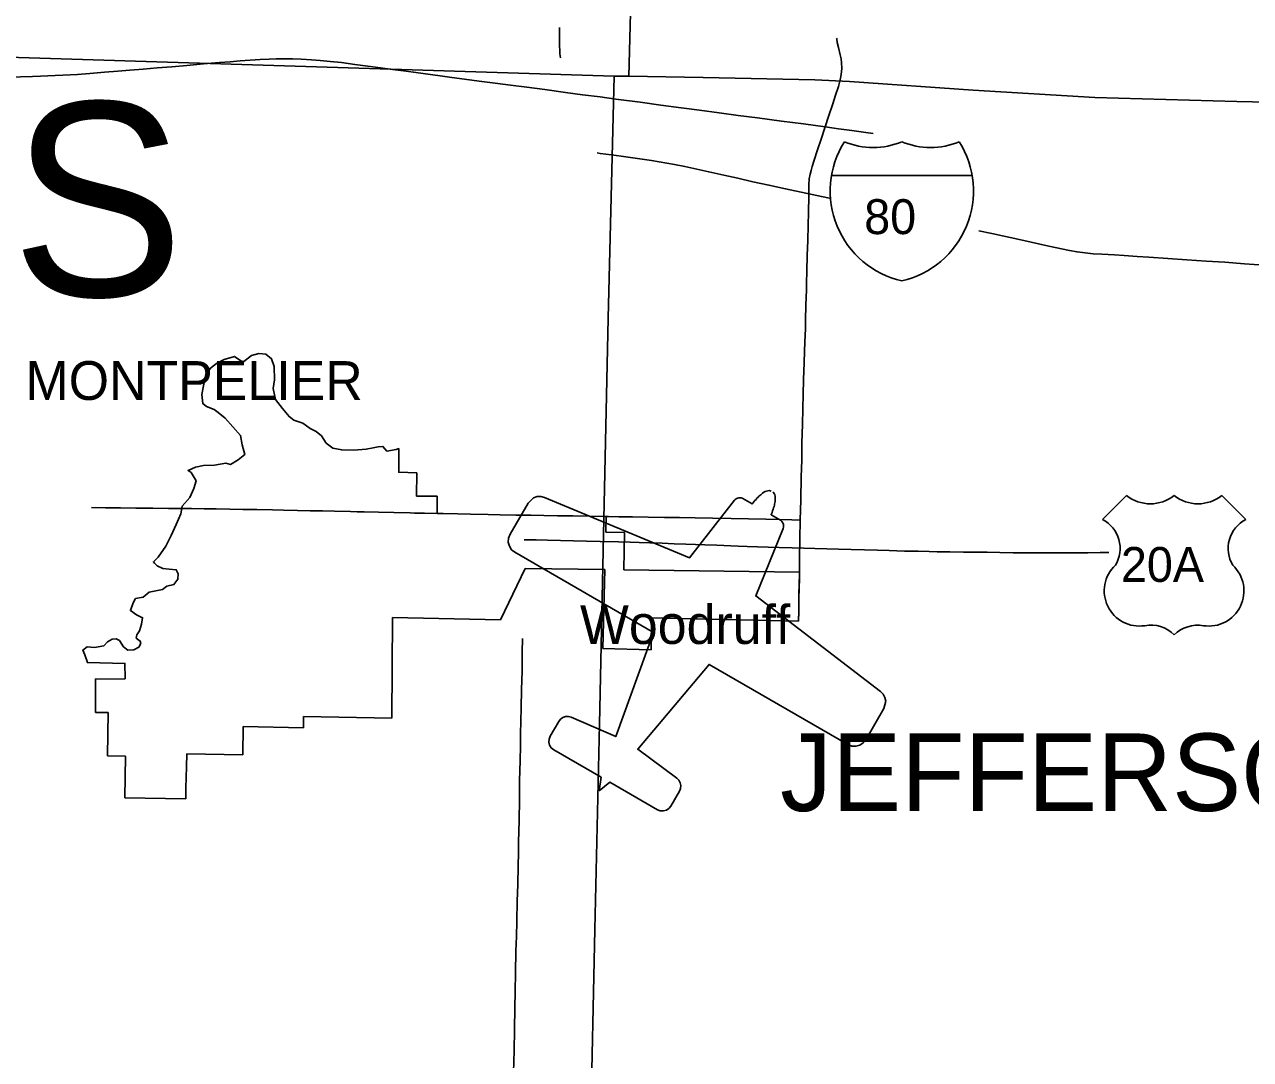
# Model space of a CAD drawing. Extents: x -232 to 448, y 619 to 1059.
# Drawn here: x -131.55 to -99.12, y 896.53 to 923.91 of the extents above; entities that cross this region are included whole.
import ezdxf

# ---------------------------------------------------------------- set-up
doc = ezdxf.new("R2010")
doc.units = 0
doc.layers.add('Default', color=7, linetype='Continuous')

msp = doc.modelspace()

# ---------------------------------------------------------------- linework, layer by layer
at = {"layer": 'Default'}
for p, q in [((-110.207, 919.917), (-106.487, 919.917)), ((-102.405, 911.449), (-103.039, 910.815)), ((-102.405, 911.449), (-103.039, 910.815)), ((-99.249, 910.815), (-99.884, 911.449)), ((-99.249, 910.815), (-99.884, 911.449)), ((-116.178, 910.485), (-116.168, 910.896)), ((-115.677, 910.472), (-116.178, 910.485)), ((-115.703, 909.487), (-115.677, 910.472)), ((-118.965, 908.164), (-118.31, 909.522)), ((-121.816, 908.226), (-118.965, 908.164)), ((-114.977, 907.371), (-114.958, 908.218)), ((-116.255, 907.401), (-114.977, 907.371)), ((-129.335, 905.708), (-129.355, 904.565)), ((-125.778, 904.593), (-125.764, 905.338)), ((-125.764, 905.338), (-124.173, 905.309)), ((-128.88, 904.556), (-128.899, 903.457)), ((-127.26, 904.619), (-125.778, 904.593)), ((-128.899, 903.457), (-127.286, 903.428))]:
    msp.add_line(p, q, dxfattribs=at)
for points in [[(-114.736, 953.989), (-115.571, 922.539)], [(-148.03, 923.551), (-115.954, 922.545)], [(-117.4, 923.827), (-117.401, 923.701), (-117.398, 923.516), (-117.4, 923.333), (-117.396, 923.23), (-117.39, 923.137), (-117.373, 923.032)], [(-110.071, 923.549), (-110.069, 923.532), (-110.054, 923.435), (-110.022, 923.305), (-109.975, 923.104), (-109.952, 923.005), (-109.938, 922.892), (-109.935, 922.758), (-109.941, 922.657), (-109.958, 922.538), (-109.982, 922.407), (-110.022, 922.272), (-110.097, 922.043), (-110.174, 921.811), (-110.284, 921.474), (-110.374, 921.204)], [(-131.977, 922.517), (-131.342, 922.531), (-131.124, 922.54), (-130.152, 922.589), (-129.826, 922.616), (-129.438, 922.649), (-129.084, 922.678), (-128.766, 922.702), (-128.413, 922.731), (-128.044, 922.762), (-127.658, 922.794), (-127.256, 922.825), (-126.817, 922.866), (-126.39, 922.902), (-126.115, 922.925), (-125.847, 922.948), (-125.581, 922.966), (-125.319, 922.981), (-125.08, 922.996), (-124.895, 923.002), (-124.711, 923.005), (-124.464, 923.001), (-124.23, 922.994), (-123.958, 922.975), (-123.728, 922.96), (-123.469, 922.934), (-123.171, 922.902), (-122.816, 922.853), (-122.467, 922.809), (-122.133, 922.762), (-121.818, 922.72), (-121.523, 922.683), (-121.262, 922.648), (-120.944, 922.606), (-120.556, 922.554), (-120.248, 922.512), (-119.917, 922.468), (-119.529, 922.414), (-119.1, 922.359), (-118.7, 922.309), (-118.266, 922.25), (-117.792, 922.186), (-117.246, 922.114), (-116.794, 922.053), (-116.322, 921.993), (-115.913, 921.938), (-115.271, 921.852), (-114.721, 921.778), (-114.185, 921.709), (-113.698, 921.644), (-113.175, 921.571), (-112.672, 921.504), (-112.165, 921.437), (-111.526, 921.355), (-110.947, 921.279), (-110.374, 921.204)], [(-115.954, 922.545), (-116.114, 916.14), (-116.231, 910.823), (-116.342, 905.4), (-116.47, 899.975), (-116.579, 894.589), (-116.727, 889.174), (-116.86, 883.788)], [(-115.571, 922.539), (-115.954, 922.545)], [(-115.571, 922.539), (-113.603, 922.507), (-110.65, 922.444), (-109.73, 922.398), (-106.457, 922.175), (-103.241, 921.98), (-99.484, 921.873), (-96.189, 921.801), (-88.422, 921.571)], [(-110.39, 921.154), (-110.471, 920.906), (-110.581, 920.567), (-110.665, 920.324), (-110.716, 920.152), (-110.745, 920.05), (-110.77, 919.95), (-110.799, 919.823), (-110.807, 919.673), (-110.809, 919.465), (-110.81, 919.237), (-110.814, 919.068)], [(-110.374, 921.204), (-110.39, 921.154)], [(-110.374, 921.204), (-110.021, 921.153), (-109.668, 921.11), (-109.302, 921.057), (-109.105, 921.029)], [(-116.407, 920.512), (-116.327, 920.501), (-116.021, 920.461), (-115.649, 920.41), (-114.964, 920.312), (-114.363, 920.21), (-114.084, 920.151), (-113.455, 920.009), (-113.055, 919.924), (-112.68, 919.842), (-112.287, 919.748), (-111.86, 919.661), (-111.42, 919.565), (-110.473, 919.358), (-110.258, 919.312)], [(-110.814, 919.068), (-110.818, 918.93), (-110.825, 918.614), (-110.836, 918.19), (-110.847, 917.808), (-110.86, 917.38), (-110.865, 917.075)], [(-106.313, 918.451), (-105.968, 918.378), (-105.2, 918.21), (-104.456, 918.046), (-103.911, 917.933), (-103.712, 917.893), (-103.498, 917.87), (-103.289, 917.845), (-103.058, 917.831), (-102.725, 917.816), (-102.461, 917.801), (-102.122, 917.776), (-101.809, 917.756), (-101.312, 917.717), (-100.805, 917.686), (-100.297, 917.651), (-99.804, 917.619), (-99.283, 917.583), (-98.773, 917.548)], [(-110.865, 917.075), (-110.869, 916.891), (-110.881, 916.488), (-110.89, 916.093), (-110.897, 915.871), (-110.911, 915.511), (-110.918, 915.27)], [(-121.718, 912.672), (-121.967, 912.622), (-122.072, 912.75), (-122.195, 912.738), (-122.327, 912.715), (-122.517, 912.676), (-122.84, 912.648), (-123.16, 912.656), (-123.396, 912.701), (-123.569, 912.835), (-123.7, 913.026), (-123.838, 913.145), (-123.991, 913.221), (-124.192, 913.363), (-124.423, 913.445), (-124.552, 913.537), (-124.723, 913.751), (-124.909, 913.988), (-124.973, 914.278), (-124.941, 914.51), (-124.949, 914.864), (-125.014, 915.068), (-125.171, 915.192), (-125.357, 915.211), (-125.547, 915.152), (-125.746, 914.996), (-125.83, 915.012), (-125.993, 915.129), (-126.272, 915.049), (-126.47, 914.944), (-126.634, 914.819), (-126.751, 914.656), (-126.817, 914.351), (-126.861, 914.127), (-126.831, 913.884), (-126.734, 913.803), (-126.532, 913.726), (-126.432, 913.649), (-126.245, 913.496), (-126.038, 913.265), (-125.838, 913.04), (-125.79, 912.795), (-125.721, 912.535), (-125.904, 912.394), (-126.105, 912.267), (-126.222, 912.304), (-126.526, 912.252), (-126.82, 912.244), (-127.026, 912.199), (-127.225, 912.11), (-127.141, 912.059), (-127.015, 911.837), (-127.071, 911.637), (-127.179, 911.396), (-127.384, 911.173)], [(-110.918, 915.27), (-110.929, 914.958), (-110.946, 914.516), (-110.959, 914.125), (-110.965, 913.755), (-110.976, 913.325), (-110.989, 912.846), (-110.994, 912.388), (-111.006, 911.944), (-111.021, 911.337), (-111.031, 910.798)], [(-121.178, 912.049), (-121.652, 912.066), (-121.653, 912.69), (-121.718, 912.672)], [(-121.187, 911.434), (-121.178, 912.049)], [(-116.351, 903.64), (-116.3, 904), (-117.553, 904.724), (-117.617, 904.775), (-117.662, 904.844), (-117.683, 904.923), (-117.678, 905.005), (-117.649, 905.081), (-117.422, 905.475), (-117.375, 905.534), (-117.312, 905.578), (-117.24, 905.602), (-117.164, 905.604), (-117.091, 905.584), (-115.911, 905.073), (-114.912, 907.829), (-118.582, 909.948), (-118.666, 910.016), (-118.726, 910.108), (-118.754, 910.214), (-118.748, 910.323), (-118.709, 910.425), (-118.232, 911.252), (-118.088, 911.389), (-117.993, 911.421), (-117.893, 911.425), (-117.795, 911.4), (-113.958, 909.805), (-112.772, 911.325), (-112.752, 911.347), (-112.731, 911.364), (-112.712, 911.374), (-112.689, 911.384), (-112.661, 911.39), (-112.63, 911.392), (-112.598, 911.388), (-112.573, 911.381), (-112.548, 911.369), (-112.303, 911.227), (-112.285, 911.251), (-112.259, 911.283), (-112.232, 911.316), (-112.203, 911.349), (-112.177, 911.377), (-112.15, 911.405), (-112.125, 911.43), (-112.102, 911.451), (-112.079, 911.471), (-112.052, 911.493), (-112.027, 911.511), (-111.992, 911.535), (-111.957, 911.554), (-111.924, 911.568), (-111.889, 911.578), (-111.858, 911.582), (-111.827, 911.578), (-111.802, 911.568)], [(-111.759, 911.544), (-111.738, 911.527), (-111.72, 911.502), (-111.707, 911.473), (-111.698, 911.437), (-111.694, 911.402), (-111.693, 911.362), (-111.696, 911.32), (-111.699, 911.29), (-111.705, 911.255), (-111.711, 911.225), (-111.718, 911.195), (-111.726, 911.16), (-111.737, 911.123), (-111.748, 911.087), (-111.763, 911.045), (-111.778, 911.005), (-111.793, 910.967), (-111.804, 910.94), (-111.559, 910.798), (-111.536, 910.782), (-111.517, 910.764), (-111.498, 910.739), (-111.484, 910.711), (-111.475, 910.683), (-111.472, 910.659), (-111.472, 910.637), (-111.476, 910.61), (-111.485, 910.582), (-112.208, 908.795), (-108.908, 906.269), (-108.838, 906.197), (-108.792, 906.109), (-108.772, 906.01), (-108.818, 905.817), (-109.296, 904.99), (-109.365, 904.905), (-109.456, 904.845), (-109.562, 904.817), (-109.671, 904.823), (-109.773, 904.862), (-113.443, 906.981), (-115.33, 904.738), (-114.297, 903.971), (-114.243, 903.917), (-114.207, 903.851), (-114.192, 903.776), (-114.198, 903.701), (-114.226, 903.63), (-114.454, 903.236), (-114.505, 903.173), (-114.574, 903.128), (-114.653, 903.107), (-114.735, 903.111), (-114.811, 903.14), (-116.065, 903.864), (-116.351, 903.64)], [(-120.636, 911.429), (-121.187, 911.434)], [(-120.636, 910.975), (-120.636, 911.429)], [(-127.384, 911.173), (-127.417, 910.967), (-127.54, 910.683), (-127.669, 910.391), (-127.81, 910.115), (-128.017, 909.82), (-128.14, 909.698), (-128.116, 909.659), (-128.039, 909.594), (-127.896, 909.522), (-127.724, 909.506), (-127.539, 909.485), (-127.485, 909.381), (-127.497, 909.237), (-127.6, 909.095), (-127.783, 909.054), (-127.899, 908.967), (-128.258, 908.896), (-128.414, 908.761), (-128.613, 908.726), (-128.679, 908.608), (-128.751, 908.408), (-128.588, 908.294), (-128.427, 908.218), (-128.458, 908.048), (-128.506, 907.868), (-128.577, 907.766), (-128.598, 907.678), (-128.493, 907.602), (-128.475, 907.534), (-128.524, 907.442), (-128.658, 907.368), (-128.818, 907.356), (-128.934, 907.45), (-129.041, 907.614), (-129.129, 907.662), (-129.232, 907.649), (-129.358, 907.577), (-129.452, 907.476), (-129.701, 907.434), (-129.892, 907.445), (-130.008, 907.364), (-129.958, 907.232), (-129.885, 907.033), (-128.897, 907.01), (-128.892, 906.605), (-129.677, 906.597), (-129.676, 905.715)], [(-129.781, 911.131), (-129.411, 911.127), (-129.302, 911.127)], [(-129.302, 911.127), (-129.015, 911.127), (-128.606, 911.12), (-128.159, 911.116), (-127.745, 911.109), (-127.49, 911.105), (-127.457, 911.105)], [(-127.457, 911.105), (-127.348, 911.104)], [(-127.348, 911.104), (-127.238, 911.104)], [(-127.238, 911.104), (-127.134, 911.103), (-126.803, 911.1)], [(-126.803, 911.1), (-126.483, 911.097), (-126.117, 911.089), (-125.78, 911.083), (-125.405, 911.08)], [(-125.405, 911.08), (-124.993, 911.072), (-124.703, 911.066), (-124.331, 911.055), (-123.991, 911.048), (-123.67, 911.041), (-123.349, 911.035), (-122.927, 911.026), (-122.755, 911.021)], [(-122.755, 911.021), (-122.567, 911.016), (-122.19, 911.01), (-121.785, 910.999), (-121.351, 910.989), (-121.237, 910.986)], [(-121.237, 910.986), (-120.968, 910.98), (-120.583, 910.974), (-120.48, 910.972)], [(-116.168, 910.896), (-116.608, 910.9), (-117.049, 910.91), (-117.45, 910.916), (-117.815, 910.923), (-118.158, 910.928), (-118.556, 910.935), (-118.967, 910.94), (-119.29, 910.949), (-119.753, 910.957), (-120.091, 910.963), (-120.583, 910.974), (-120.636, 910.975)], [(-120.48, 910.972), (-120.091, 910.963), (-119.753, 910.957), (-119.29, 910.949), (-118.967, 910.94), (-118.556, 910.935), (-118.158, 910.928), (-117.815, 910.923), (-117.45, 910.916), (-117.049, 910.91), (-116.608, 910.9), (-116.221, 910.897), (-116.216, 910.897)], [(-116.216, 910.897), (-116.107, 910.895)], [(-116.107, 910.895), (-115.828, 910.891), (-115.47, 910.885), (-115.054, 910.878), (-114.626, 910.872), (-114.229, 910.865), (-113.815, 910.864), (-113.354, 910.854), (-112.858, 910.841), (-112.399, 910.831), (-111.946, 910.823), (-111.582, 910.815), (-111.253, 910.805), (-111.031, 910.798)], [(-111.031, 910.798), (-111.045, 910.305), (-111.053, 909.768), (-111.053, 909.491)], [(-118.332, 910.281), (-118.014, 910.277), (-117.721, 910.271), (-117.376, 910.264), (-117.026, 910.254), (-116.684, 910.245), (-116.328, 910.238), (-115.842, 910.228), (-115.533, 910.219), (-115.293, 910.21), (-115.007, 910.202), (-114.686, 910.187), (-114.365, 910.176), (-114.06, 910.163), (-113.799, 910.154), (-113.554, 910.145), (-113.237, 910.134), (-112.867, 910.118), (-112.675, 910.112), (-112.437, 910.105), (-112.163, 910.095), (-111.883, 910.087), (-111.589, 910.074), (-111.247, 910.065), (-110.939, 910.057), (-110.648, 910.049), (-110.331, 910.038), (-110.017, 910.029), (-109.683, 910.02), (-109.333, 910.013), (-108.99, 910.003), (-108.677, 909.993), (-108.275, 909.98), (-107.913, 909.975), (-107.627, 909.967), (-107.413, 909.962), (-107.073, 909.959), (-106.715, 909.954), (-106.441, 909.952), (-106.087, 909.949), (-105.752, 909.942), (-105.4, 909.938), (-105.06, 909.937), (-104.772, 909.935), (-104.504, 909.936), (-104.162, 909.937), (-103.793, 909.937), (-103.429, 909.938), (-103.097, 909.943), (-102.869, 909.939)], [(-118.31, 909.522), (-116.202, 909.494)], [(-116.202, 909.494), (-116.255, 907.401)], [(-111.054, 909.426), (-115.703, 909.487)], [(-111.077, 908.126), (-111.076, 908.192), (-111.074, 908.316), (-111.067, 908.836), (-111.054, 909.368), (-111.054, 909.426)], [(-111.053, 909.491), (-111.054, 909.35), (-111.065, 908.891)], [(-111.07, 908.619), (-111.071, 908.51)], [(-111.065, 908.891), (-111.067, 908.836), (-111.07, 908.619)], [(-111.071, 908.51), (-111.073, 908.353), (-111.076, 908.182)], [(-121.838, 905.564), (-121.816, 908.226)], [(-114.958, 908.218), (-111.077, 908.126)], [(-118.378, 907.666), (-118.384, 907.308), (-118.392, 906.812), (-118.403, 906.312), (-118.411, 905.839), (-118.419, 905.471), (-118.43, 905.157), (-118.435, 904.83), (-118.443, 904.439), (-118.456, 903.905), (-118.46, 903.421), (-118.467, 902.845), (-118.481, 902.288), (-118.486, 902.006), (-118.496, 901.647), (-118.504, 901.161), (-118.517, 900.721), (-118.529, 900.195), (-118.54, 899.784), (-118.552, 899.395), (-118.561, 898.823), (-118.571, 898.334), (-118.582, 897.898), (-118.594, 897.324), (-118.603, 896.759), (-118.617, 896.197)], [(-129.676, 905.715), (-129.335, 905.708)], [(-124.173, 905.309), (-124.168, 905.608)], [(-124.168, 905.608), (-121.838, 905.564)], [(-129.355, 904.565), (-128.88, 904.556)], [(-127.286, 903.428), (-127.28, 903.713), (-127.267, 904.272), (-127.26, 904.619)]]:
    msp.add_lwpolyline(points, dxfattribs=at)
for centre, radius, start, end in [((-107.796, 919.508), 2.445, 147.8216, 256.9941), ((-107.796, 919.508), 2.445, 147.8216, 256.9941), ((-109.106, 922.607), 1.951, 247.0848, 292.9105), ((-109.106, 922.607), 1.951, 247.0848, 292.9105), ((-108.897, 919.508), 2.445, 283.0065, 32.1787), ((-107.587, 922.607), 1.951, 247.0916, 292.9084), ((-108.897, 919.508), 2.445, 283.0065, 32.1787), ((-107.587, 922.607), 1.951, 247.0916, 292.9084), ((-101.774, 912.25), 1.019, 231.813, 308.187), ((-101.774, 912.25), 1.019, 231.813, 308.187), ((-100.514, 912.25), 1.019, 231.813, 308.187), ((-100.514, 912.25), 1.019, 231.813, 308.187), ((-103.435, 910.049), 0.862, 329.1175, 62.6108), ((-103.435, 910.049), 0.862, 329.1175, 62.6108), ((-98.853, 910.049), 0.862, 117.3892, 210.8825), ((-98.853, 910.049), 0.862, 117.3892, 210.8825), ((-102.061, 908.927), 0.93, 133.0046, 278.7282), ((-102.061, 908.927), 0.93, 133.0046, 278.7282), ((-100.227, 908.927), 0.93, 261.2718, 46.9954), ((-100.227, 908.927), 0.93, 261.2718, 46.9954), ((-101.749, 907.193), 0.832, 43.4177, 101.8742), ((-101.749, 907.193), 0.832, 43.4177, 101.8742), ((-100.522, 907.137), 0.883, 79.9613, 134.7468), ((-100.522, 907.137), 0.883, 79.9613, 134.7468)]:
    msp.add_arc(centre, radius, start, end, dxfattribs=at)

# ---------------------------------------------------------------- texts
for s, height, p in [('WILLIAMS', 5.13, (-160.112, 916.722)), ('80', 0.9234, (-109.341, 918.365)), ('MONTPELIER', 1.026, (-131.525, 913.979)), ('20A', 0.9234, (-102.551, 909.165)), ('Woodruff                   ', 1.026, (-116.86, 907.524)), ('JEFFERSON', 2.052, (-111.565, 903.104))]:
    msp.add_text(s, height=height, dxfattribs=at).set_placement(p)

doc.saveas('drawing.dxf')
